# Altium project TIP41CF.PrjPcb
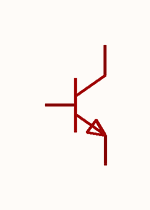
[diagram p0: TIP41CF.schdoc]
1 sheet, 1 parts. Net scope: global (net labels, ports and power ports of the same name join across sheets).

## Sheet TIP41CF.schdoc
size 127 x 101 mm

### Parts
Q?  tip41cf  [TO-220FP-3_L10.0-W4.8-P2.54-L]  (value not drawn)

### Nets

Not connected (* = marked no-connect by the designer): Q? 1(B) 2(C) 3(E)

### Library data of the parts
Q? = tip41cf: 晶体管类型:NPN;集电极电流(Ic):6A;集射极击穿电压(Vceo):100V;耗散功率(Pd):2W;直流电流增益(hFE):30;; Manufacturer: CJ(江苏长电/长晶); AddInBom: yes; ModelId: 590d5e0c845248b0ab2d7a54f92afb29; ModelTransform: 393.7,177.165,0,0,0,0,0,25.591,-137.795; type: NPN; Current - Collector(Ic): 6A; Collector - Emitter Voltage VCEO: 100V; Pd - Power Dissipation: 2W; DC Current Gain: 30; Transition frequency(fT): 3MHz; Current - Collector Cutoff: 400uA; Vce Saturation(VCE(sat)): 1.5V; Emitter-Base Voltage(Vebo): 5V; Number: 1个NPN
